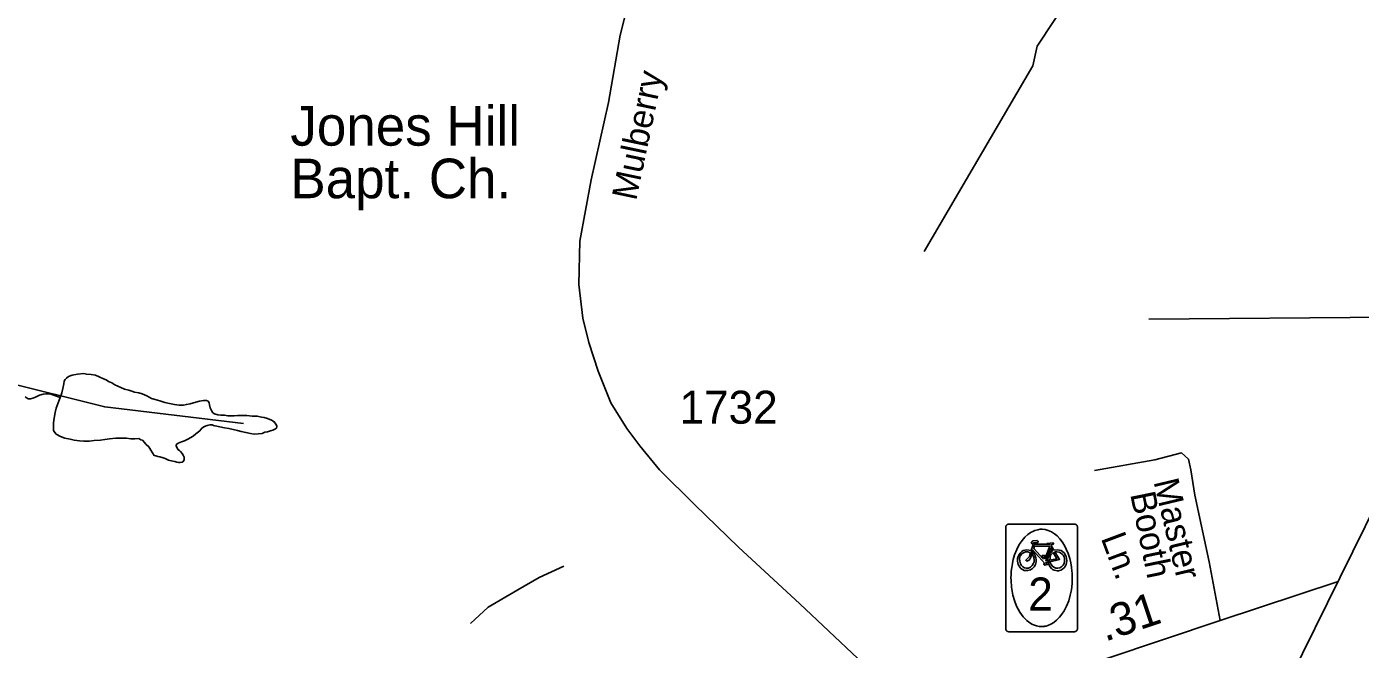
# Model space of a CAD drawing. Extents: x 2126262 to 2293712, y 749403 to 919119.
# Drawn here: x 2232664 to 2237712, y 788270 to 790629 of the extents above; entities that cross this region are included whole.
import ezdxf

# ---------------------------------------------------------------- set-up
doc = ezdxf.new("R2010")
doc.units = 0
for name, color, linetype in [('Exist Boundary Political CountyLine', 7, 'Continuous'), ('Exist Cultural Church with Cemetery Label', 7, 'Continuous'), ('Exist Hydrographic Misc Water Feature', 7, 'Continuous'), ('Exist Road Non-System Type 51', 7, 'Continuous'), ('Exist Road Non-System Type 51 Label', 7, 'Continuous'), ('Exist Road Secondary Bike CELL', 7, 'Continuous'), ('Exist Road Secondary Mileage Hundredths English Label', 7, 'Continuous'), ('Exist Road Secondary Type 51 Attributed', 7, 'Continuous'), ('Exist Road Secondary Type 51 Label', 7, 'Continuous'), ('Exist Road Secondary Type 51 Number Label', 7, 'Continuous'), ('Map Preparation Longitude Latitude Lines', 7, 'Continuous')]:
    doc.layers.add(name, color=color, linetype=linetype)

msp = doc.modelspace()

# ---------------------------------------------------------------- linework, layer by layer
at = {"layer": 'Exist Boundary Political CountyLine'}
msp.add_lwpolyline([(2293117.8, 894131.3), (2291903.9, 891776.4), (2258821.6, 829664.6), (2255410.5, 823324), (2242088.6, 797598.7), (2231459.6, 775980.5), (2225010.8, 762953.2), (2220565.7, 753519.8)], dxfattribs=at)
at = {"layer": 'Exist Hydrographic Misc Water Feature'}
for points in [[(2236061.3, 789777.2), (2236472.5, 790480.5), (2236488.5, 790555.6), (2236677.3, 790840.4)], [(2233484.4, 789125.1), (2232959.3, 789188.4), (2232183.4, 789381.5)], [(2233516.7, 789153.5), (2233496.6, 789155.3), (2233478.6, 789155.2), (2233463, 789155), (2233448.8, 789154.9), (2233434.9, 789154.8), (2233424.8, 789154.7), (2233412.9, 789156.6), (2233398.8, 789156.5), (2233386.9, 789158.4), (2233374.6, 789162.3), (2233368.6, 789166.2), (2233362.7, 789174.2), (2233358.6, 789184.2), (2233356.3, 789196.2), (2233354.3, 789204.1), (2233350.4, 789210.1), (2233344.5, 789212), (2233332.4, 789211.9), (2233318.4, 789209.8), (2233304.5, 789205.7), (2233282.3, 789199.5), (2233268.4, 789197.4), (2233256.7, 789195.3), (2233240.7, 789195.2), (2233222.6, 789197), (2233204.4, 789200.9), (2233186.4, 789204.7), (2233168.3, 789210.6), (2233150.5, 789216.4), (2233136.3, 789220.3), (2233118.5, 789230.2), (2233100.2, 789238), (2233088.1, 789241.9), (2233072.1, 789243.8), (2233062.1, 789247.7), (2233050.2, 789251.6), (2233034.2, 789255.5), (2233020.1, 789261.4), (2232997.9, 789271.2), (2232985.8, 789279.1), (2232973.9, 789285), (2232963.9, 789290.9), (2232953.8, 789294.8), (2232937.8, 789302.7), (2232923.7, 789308.5), (2232907.7, 789310.4), (2232889.6, 789312.3), (2232879.6, 789314.2), (2232855.6, 789312), (2232835.9, 789307.9), (2232822, 789303.8), (2232814, 789297.7), (2232809.9, 789291.6), (2232806, 789285.6), (2232804.1, 789275.6), (2232800, 789257.6), (2232796.3, 789241.5), (2232790.4, 789223.5)], [(2232790.4, 789223.5), (2232768.5, 789231.3), (2232758.4, 789235.2), (2232750.4, 789237.2), (2232744.5, 789237.1), (2232736.5, 789237.1), (2232726.4, 789237), (2232712.5, 789232.9), (2232704.5, 789228.8), (2232696.5, 789224.7), (2232686.6, 789220.7), (2232678.6, 789218.6), (2232668.6, 789218.6), (2232658.3, 789226.4)], [(2232790.4, 789223.5), (2232782.6, 789203.5), (2232774.8, 789183.4), (2232770.9, 789167.3), (2232767.2, 789145.4), (2232765.4, 789127.4), (2232765.4, 789115.4), (2232765.4, 789105.4), (2232765.4, 789099.4), (2232769.7, 789091.4), (2232775.6, 789085.4), (2232791.6, 789075.6), (2232807.6, 789069.7), (2232827.7, 789065.8), (2232843.9, 789062), (2232863.8, 789060.2), (2232879.8, 789058.3), (2232899.9, 789058.5), (2232919.6, 789060.6), (2232943.6, 789062.8), (2232959.6, 789065), (2232977.6, 789067.1), (2233001.6, 789069.3), (2233017.6, 789069.4), (2233041.6, 789069.6), (2233057.6, 789067.7), (2233073.6, 789067.8), (2233087.7, 789068), (2233095.7, 789064), (2233101.7, 789062.1), (2233115.8, 789046.2), (2233125.9, 789036.3), (2233133.9, 789024.4), (2233140.2, 789014.4), (2233146.2, 789004.5), (2233152.1, 789002.5), (2233160.1, 789000.6), (2233168.1, 788998.7), (2233180.2, 788994.8), (2233188.2, 788992.8), (2233200.1, 788986.9), (2233216.3, 788983.1), (2233224.3, 788981.2), (2233232.3, 788979.3), (2233238.4, 788977.3), (2233244.4, 788977.3), (2233252.4, 788979.4), (2233256.5, 788981.4), (2233260.2, 788987.4), (2233260.2, 788997.4), (2233256.1, 789005.4), (2233252.2, 789011.4), (2233245.8, 789019.3), (2233241.9, 789023.3), (2233236, 789027.2), (2233231.9, 789035.2), (2233229.8, 789039.2), (2233229.8, 789043.2), (2233231.7, 789047.2), (2233237.6, 789051.2), (2233249.7, 789055.3), (2233261.6, 789059.4), (2233273.7, 789065.5), (2233293.4, 789077.7), (2233303.4, 789085.7), (2233319.4, 789097.9), (2233327.2, 789107.9), (2233337.1, 789114), (2233347.1, 789118.1), (2233357.2, 789120.2), (2233365.2, 789120.2), (2233371.1, 789118.3), (2233377.1, 789116.3), (2233395.1, 789112.5), (2233413.1, 789108.6), (2233429.1, 789106.8), (2233445.1, 789102.9), (2233461.1, 789099.1), (2233475.1, 789095.2), (2233493.3, 789091.3), (2233511.4, 789087.4), (2233525.3, 789085.5), (2233539.5, 789085.7), (2233555.4, 789087.8), (2233565.1, 789091.9), (2233575.1, 789094), (2233587.2, 789098), (2233595.2, 789100.1), (2233603.2, 789104.2), (2233609.2, 789108.2), (2233611.2, 789112.2), (2233611.2, 789116.2), (2233606.9, 789122.2), (2233601, 789132.2), (2233590.9, 789138.1), (2233574.9, 789143.9), (2233562.8, 789147.9), (2233553, 789149.8), (2233536.6, 789153.6), (2233516.7, 789153.5)], [(2234523.3, 788494.9), (2234603.9, 788541.7), (2234697.6, 788584.2)], [(2234343.9, 788367.9), (2234411.1, 788429.6), (2234523.3, 788494.9)]]:
    msp.add_lwpolyline(points, dxfattribs=at)
at = {"layer": 'Exist Road Non-System Type 51'}
msp.add_lwpolyline([(2237181.4, 788379.2), (2237140, 788601.1), (2237085.7, 788853.5), (2237070.4, 788949.2), (2237061.7, 788990.6), (2237035.5, 789014), (2236934.7, 788987.1), (2236706, 788946.7)], dxfattribs=at)
at = {"layer": 'Exist Road Secondary Bike CELL'}
for points in [[(2236380.3, 788743.9), (2236381.2, 788743.9), (2236414.2, 788743.9), (2236597.6, 788743.9), (2236630.6, 788743.9), (2236631.8, 788743.8), (2236632.4, 788743.7), (2236633.1, 788743.6), (2236633.9, 788743.4), (2236634.6, 788743.1), (2236635.9, 788742.4), (2236636.5, 788742.1), (2236637.1, 788741.6), (2236637.9, 788741), (2236638.8, 788740), (2236639.4, 788739.2), (2236639.7, 788738.7), (2236639.9, 788738.4), (2236640.2, 788737.9), (2236640.4, 788737.4), (2236640.6, 788737), (2236640.8, 788736.2), (2236641.1, 788735.3), (2236641.2, 788734.4), (2236641.3, 788734), (2236641.3, 788733.7), (2236641.3, 788700.2), (2236641.3, 788380.3), (2236641.3, 788347.2), (2236641.2, 788346), (2236641.1, 788345.4), (2236640.9, 788344.7), (2236640.7, 788343.9), (2236640.5, 788343.2), (2236639.8, 788341.9), (2236639.4, 788341.3), (2236639, 788340.7), (2236638.4, 788339.9), (2236637.9, 788339.5), (2236637.4, 788339), (2236637, 788338.7), (2236636.5, 788338.4), (2236636.1, 788338.1), (2236635.7, 788337.9), (2236635.2, 788337.6), (2236634.4, 788337.2), (2236633.6, 788337), (2236632.7, 788336.7), (2236632.2, 788336.7), (2236631.8, 788336.6), (2236631.4, 788336.5), (2236631, 788336.5), (2236630.5, 788336.5), (2236597.5, 788336.5), (2236414.2, 788336.5), (2236381.2, 788336.5), (2236380.6, 788336.6), (2236380, 788336.6), (2236379.4, 788336.7), (2236378.6, 788336.9), (2236377.9, 788337.1), (2236377.2, 788337.3), (2236376.5, 788337.7), (2236375.8, 788338), (2236375.2, 788338.4), (2236374.6, 788338.8), (2236374.3, 788339.1), (2236373.9, 788339.4), (2236373.6, 788339.7), (2236373.2, 788340.1), (2236372.9, 788340.5), (2236372.5, 788341), (2236372.2, 788341.4), (2236372, 788341.9), (2236371.6, 788342.4), (2236371.4, 788342.9), (2236371.2, 788343.5), (2236371.1, 788343.8), (2236371, 788344.1), (2236370.9, 788344.3), (2236370.8, 788344.5), (2236370.8, 788344.8), (2236370.7, 788345), (2236370.7, 788345.3), (2236370.6, 788345.5), (2236370.6, 788345.7), (2236370.5, 788346), (2236370.5, 788346.2), (2236370.5, 788346.5), (2236370.5, 788347.1), (2236370.4, 788380.2), (2236370.4, 788700.2), (2236370.4, 788733.2), (2236370.5, 788734.4), (2236370.6, 788735), (2236370.8, 788735.8), (2236371, 788736.5), (2236371.3, 788737.2), (2236371.9, 788738.5), (2236372.3, 788739.2), (2236372.8, 788739.8), (2236373.4, 788740.5), (2236374.4, 788741.4), (2236375.2, 788742.1), (2236375.6, 788742.3), (2236376, 788742.5), (2236376.5, 788742.8), (2236376.9, 788743), (2236377.4, 788743.2), (2236378.1, 788743.5), (2236379.1, 788743.7), (2236380, 788743.8)], [(2236505.8, 788356), (2236501.2, 788356.2), (2236496.8, 788356.6), (2236486.8, 788358.3), (2236475.6, 788362.4), (2236469.1, 788365.6), (2236463.8, 788368.6), (2236458.1, 788372.5), (2236450.1, 788378.3), (2236436.4, 788392.2), (2236422.9, 788410.2), (2236411, 788433.4), (2236402.8, 788454.2), (2236397.5, 788474.7), (2236391.9, 788505.5), (2236390, 788529.9), (2236389.9, 788541.8), (2236390.1, 788550.5), (2236390.4, 788556.6), (2236391.1, 788566), (2236392.5, 788580.3), (2236395.1, 788594.9), (2236397.1, 788604.3), (2236398.5, 788609.5), (2236401.2, 788619.2), (2236403.7, 788627.6), (2236411.6, 788648.2), (2236421.4, 788666.7), (2236432.2, 788682.3), (2236441.8, 788694.1), (2236453.3, 788704.8), (2236462.2, 788710.8), (2236466.8, 788713.6), (2236472, 788716.4), (2236480.6, 788720.3), (2236491, 788722.9), (2236500.3, 788724.4), (2236508, 788724.6), (2236518.9, 788723.5), (2236530.3, 788720.4), (2236543.3, 788714.8), (2236554.6, 788707.8), (2236564.3, 788699.6), (2236575, 788688.5), (2236583.7, 788677.2), (2236592.3, 788663.3), (2236599.4, 788649.7), (2236606.5, 788632.4), (2236612.1, 788614.4), (2236616.1, 788597.4), (2236619.1, 788580.8), (2236620.6, 788566.2), (2236621.1, 788558.1), (2236622.1, 788539.1), (2236621.2, 788518.8), (2236618.5, 788495.1), (2236614.2, 788474.5), (2236608.4, 788453.6), (2236600.5, 788433.4), (2236591.4, 788415.9), (2236582.9, 788402.7), (2236574, 788391.3), (2236562.8, 788379.6), (2236552.5, 788371.3), (2236541.2, 788364.7), (2236529.8, 788359.9), (2236522.7, 788358), (2236518.5, 788357.2), (2236515.1, 788356.6), (2236511.2, 788356.3)], [(2236525.3, 788670.7), (2236549.4, 788673.5), (2236551.2, 788671.7), (2236549.8, 788668), (2236543.8, 788666.2), (2236542.3, 788662.9), (2236552.4, 788645.8), (2236566.9, 788646.5), (2236579.7, 788643.6), (2236591, 788635.1), (2236596.3, 788626.5), (2236598.9, 788621.8), (2236600.7, 788614.1), (2236601.1, 788605.9), (2236600.1, 788597.3), (2236598.3, 788590.9), (2236594.6, 788584), (2236591.1, 788578.8), (2236584.4, 788573.4), (2236578.3, 788569.8), (2236569.9, 788567.7), (2236564.6, 788567.5), (2236553.8, 788569.2), (2236547, 788572.7), (2236543.6, 788575.5), (2236538.4, 788582), (2236535, 788588.1), (2236530.4, 788600.3), (2236529.3, 788606.2), (2236536.7, 788600.8), (2236542.5, 788591), (2236546.7, 788584.3), (2236552, 788580.5), (2236560.2, 788577.1), (2236566.3, 788577), (2236574.4, 788578.8), (2236581.9, 788583.1), (2236587.4, 788588.4), (2236591.7, 788595.5), (2236593.1, 788605.6), (2236592.8, 788613.7), (2236591, 788620.5), (2236587.5, 788626.6), (2236583.9, 788630.8), (2236577.9, 788635.4), (2236572.2, 788637.2), (2236562.9, 788639), (2236556.4, 788639.7), (2236573.9, 788610.1), (2236536.7, 788600.8), (2236529.3, 788606.2), (2236563.5, 788612.3), (2236549.3, 788636.8), (2236539.4, 788626.2), (2236536.6, 788607.7), (2236529.3, 788606.2), (2236529.7, 788614), (2236532.8, 788625.8), (2236538.3, 788634), (2236546, 788642.9), (2236541.1, 788653.4), (2236522.3, 788605.4), (2236529.5, 788606.2), (2236530.4, 788600.3), (2236521.9, 788599.3), (2236523.8, 788594.1), (2236528.8, 788591.4), (2236516.2, 788588.5), (2236513.1, 788592.4), (2236517.7, 788594.9), (2236473, 788645.9), (2236471.3, 788641.1), (2236477.5, 788632.8), (2236481.6, 788624.8), (2236484.4, 788616.2), (2236485.8, 788608.8), (2236485, 788601.2), (2236482.9, 788591.4), (2236478, 788582.4), (2236471.2, 788575.7), (2236463.4, 788570.9), (2236453.8, 788568.6), (2236446.8, 788568), (2236439.7, 788568.9), (2236427.4, 788576.4), (2236423.3, 788581), (2236417.6, 788591.3), (2236415.2, 788604.3), (2236415, 788613.5), (2236417.4, 788621.6), (2236421, 788629), (2236425.2, 788634.3), (2236431.2, 788640.2), (2236436.6, 788643.6), (2236443.4, 788645.7), (2236450.4, 788646.3), (2236465.7, 788644.6), (2236469.2, 788636.4), (2236464.5, 788617.5), (2236458.5, 788607.5), (2236449.6, 788603.4), (2236446.1, 788606.9), (2236460.4, 788621.4), (2236463.5, 788635.1), (2236460.3, 788636.5), (2236454.3, 788638.5), (2236444.7, 788638.7), (2236439.3, 788637.1), (2236431.9, 788632.8), (2236424.8, 788623.5), (2236421.7, 788613.8), (2236422.9, 788603.1), (2236425.7, 788593.1), (2236429.2, 788586.7), (2236434.2, 788582.8), (2236441.5, 788578.3), (2236448, 788577.1), (2236456, 788577.7), (2236463.8, 788581), (2236470.5, 788587.8), (2236474.8, 788595.9), (2236477.2, 788601.7), (2236477.9, 788609.1), (2236476.9, 788617), (2236473.1, 788626.1), (2236465.7, 788644.6), (2236473.4, 788666.4), (2236478.8, 788660.7), (2236475.8, 788652.2), (2236511.4, 788612.3), (2236510.4, 788617.4), (2236506.7, 788623.7), (2236508.3, 788625.1), (2236518.6, 788625.1), (2236516.6, 788617.8), (2236517.7, 788612.6), (2236536.6, 788660.3), (2236478.8, 788660.7), (2236473.4, 788666.4), (2236466.7, 788673.5), (2236472.4, 788680.2), (2236487.7, 788682.2), (2236493.8, 788677.4), (2236490.6, 788673.1), (2236481.3, 788674.1), (2236474.9, 788672.7), (2236476.3, 788671.4), (2236479.6, 788671.4), (2236478.1, 788668.2), (2236537.4, 788667.6), (2236537.8, 788669.1)]]:
    msp.add_lwpolyline(points, close=True, dxfattribs=at)
at = {"layer": 'Exist Road Secondary Type 51 Attributed'}
for points in [[(2236064.2, 788002.8), (2235919.9, 788131.7), (2235590.5, 788442), (2235358.1, 788656.5), (2235193.4, 788817.3), (2235059.4, 788950.1), (2234985.3, 789040.8), (2234935.5, 789105.9), (2234875.5, 789204.2), (2234827, 789324.2), (2234791.3, 789432.8), (2234769.5, 789524.7), (2234754.2, 789652.4), (2234758.1, 789815.8), (2234800.2, 790048.2), (2234866.2, 790341.9), (2234910, 790597.2), (2234948.3, 790747.8)], [(2236064.2, 788002.8), (2236258.4, 788068.8), (2236749.6, 788233.6), (2237181.4, 788379.2), (2237628.4, 788527.1)]]:
    msp.add_lwpolyline(points, dxfattribs=at)
at = {"layer": 'Map Preparation Longitude Latitude Lines'}
msp.add_line((2236911.5, 789520.8), (2245734.6, 789591.2), dxfattribs=at)

# ---------------------------------------------------------------- texts
at = {"layer": 'Exist Cultural Church with Cemetery Label'}
for s, p in [('Jones Hill', (2233661.8, 790178)), ('Bapt. Ch.', (2233661.8, 789978.8))]:
    msp.add_text(s, height=150, dxfattribs=at).set_placement(p)
at = {"layer": 'Exist Road Non-System Type 51 Label'}
for s, rotation, p in [('Master', 283.4366, (2236929.2, 788905.3)), ('Booth', 281.5746, (2236840.8, 788857.8)), ('Ln.', 290.6063, (2236729.1, 788691.3))]:
    msp.add_text(s, height=95, rotation=rotation, dxfattribs=at).set_placement(p)
at = {"layer": 'Exist Road Secondary Bike CELL'}
msp.add_text('2', height=125, dxfattribs=at).set_placement((2236455.3, 788416.8))
at = {"layer": 'Exist Road Secondary Mileage Hundredths English Label'}
msp.add_text('.31', height=125, rotation=18.4901, dxfattribs=at).set_placement((2236745.7, 788298.2))
at = {"layer": 'Exist Road Secondary Type 51 Label'}
msp.add_text('Mulberry', height=95, rotation=78.1189, dxfattribs=at).set_placement((2234970.8, 789966.7))
at = {"layer": 'Exist Road Secondary Type 51 Number Label'}
msp.add_text('1732', height=125, dxfattribs=at).set_placement((2235134.9, 789124.5))

doc.saveas('drawing.dxf')
